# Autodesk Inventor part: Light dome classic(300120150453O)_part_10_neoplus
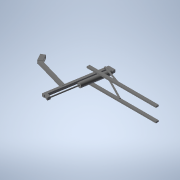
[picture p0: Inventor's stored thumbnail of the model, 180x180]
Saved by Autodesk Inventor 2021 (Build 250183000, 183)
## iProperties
Created: 2026-04
Part Number: Light dome classic(300120150453O)_part_10_neoplus
Material: Generic
Catalog Web Link: www.3dfindit.com
Description: Light dome classic_part_10_neoplus-
Vendor: KINGSPAN
Document SubType Name: Modeling
Designer: psAdmin
Manufacturer: KINGSPAN
Mass: 5302.09 g
Surface Area: 6461.21 cm^2
Volume: 5302.09 cm^3
Density: 1 g/cm^3
Appearance: PSOLRGB-255-255-255
Category: PARTsolutions
Company: KINGSPAN
Title: Light dome classic(300120150453O)_part_10_neoplus
Author: Cadenas PARTsolutions
PSOL_IDENT_0: {$CADENAS_DATA/23d-libs/kingspan_kla/light_dome_classic_neoplus/parts/part_10.prj},291 {VTYP=3D},{NB=
PSOL_IDENT_1: Light dome classic(300120150453O)_part_10_neoplus},{LINA=Light dome classic(300120150453O)_part_10_n
PSOL_IDENT_2: eoplus},{NN=Light dome classic_part_10_neoplus},{DATE=15.07.2024 10:56:16},{GEOMDATE=01.07.2024 07:0
PSOL_IDENT_3: 4:16},{VERSION=},{LINEID=10},{WBVAR=LODLEVEL,L,W,DP,OP,BA,OC},{WBNUMERIC=W}  {NB=Light dome classic(
PSOL_IDENT_4: 300120150453O)_part_10_neoplus},{LINA=Light dome classic(300120150453O)_part_10_neoplus},{KT=DUMMY},
PSOL_IDENT_5: {IDNR=},{PN=Light dome classic},{LODLEVEL=300},{L=120},{W=150},{DRIVE=1},{WX=120,150,180,240,270,300
PSOL_IDENT_6: },{DP=4},{OP=5},{BA=3},{OC=O},{OPX='5','Pneumatic - NRWG F.6 LK'},{LX=1200},{XWX=1500},{HEI=1181.607
PSOL_IDENT_7: },{VER=2},{DPX='3', 'Fixed','1', 'Natural ventilation' ,'4','NSHE', '2', 'NSHEV'}
NB: Light dome classic(300120150453O)_part_10_neoplus
NN: Light dome classic_part_10_neoplus
NBSYN: $PN.($LODLEVEL.$L.$W.$DP.$OP.$BA.$OC.)_part_10_neoplus
LINA: Light dome classic(300120150453O)_part_10_neoplus
CATALOG: Light + Air
PN: Light dome classic
LODLEVEL: 300
L: 120
W: 150
DP: NSHE
OP: Pneumatic - NRWG F.6 LK
BA: PVC base 50 cm
OC: Open
SUPPLIER: KINGSPAN
ARTICLENO: Light dome classic(300120150453O)_part_10_neoplus
BOMINFO: Light dome classic(300120150453O)_part_10_neoplus
CREATOR: CADENAS GmbH
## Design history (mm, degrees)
sketch "Sketch_2"
  geometry: L1 (-524.928, -221.6)-(-511.377, -261.6); L2 (-511.377, -261.6)-(511.377, -261.6); L3 (511.377, -261.6)-(524.928, -221.6); L4 (524.928, -221.6)-(-524.928, -221.6)
  constraints: 8 end point
extrude "Extrusion1" join sketch "Sketch_2" distance "d0" = 20; taper "d1" = 0 deg
sketch "Sketch_1"
  geometry: L1 (542.69, 169.17)-(500.978, 292.296); L2 (500.978, 292.296)-(494.348, 290.05); L3 (494.348, 290.05)-(536.06, 166.924); L4 (536.06, 166.924)-(542.69, 169.17)
  constraints: 8 end point
extrude "Extrusion2" join sketch "Sketch_1" stored distance "d2" = 220; taper "d3" = 0 deg
sketch "Sketch_3"
  geometry: L1 (-494.348, 290.05)-(-500.978, 292.296); L2 (-500.978, 292.296)-(-542.69, 169.17); L3 (-542.69, 169.17)-(-536.06, 166.924); L4 (-536.06, 166.924)-(-494.348, 290.05)
  constraints: 8 end point
extrude "Extrusion3" join sketch "Sketch_3" stored distance "d4" = 220; taper "d5" = 0 deg
sketch "Sketch_4"
  geometry: L1 (-524.928, -221.6)-(-511.377, -261.6); L2 (-511.377, -261.6)-(511.377, -261.6); L3 (511.377, -261.6)-(524.928, -221.6); L4 (524.928, -221.6)-(-524.928, -221.6)
  constraints: 8 end point
extrude "Extrusion4" join sketch "Sketch_4" distance "d6" = 20; taper "d7" = 0 deg
sketch "Sketch_5"
  geometry: L1 (446.574, 66.971)-(48.269, 244.308); L2 (48.269, 244.308)-(40.134, 226.037); L3 (40.134, 226.037)-(438.44, 48.7); L4 (438.44, 48.7)-(446.574, 66.971)
  constraints: 8 end point
extrude "Extrusion5" join sketch "Sketch_5" stored distance "d8" = 172.9; taper "d9" = 0 deg
sketch "Sketch_8"
  geometry: L1 (5, 420)-(53.95, 27.63); L2 (53.95, 27.63)-(118.95, 27.63); L3 (118.95, 27.63)-(167.9, 420); L4 (167.9, 420)-(167.9, 440); L5 (167.9, 440)-(5, 440); L6 (5, 440)-(5, 420)
  constraints: 12 end point
extrude "Extrusion6" cut sketch "Sketch_8" distance "d10" = 30; taper "d11" = 0 deg
sketch "Sketch_15"
  geometry: L1 (0, 0)-(172.9, 0); L2 (172.9, 0)-(172.9, 419.685); L3 (172.9, 419.685)-(120.498, 5); L4 (120.498, 5)-(52.402, 5); L5 (52.402, 5)-(0, 419.685); L6 (0, 419.685)-(0, 0)
  constraints: 12 end point
extrude "Extrusion7" cut sketch "Sketch_15" distance "d12" = 30; taper "d13" = 0 deg
sketch "Sketch_9"
  geometry: L1 (572.69, 832.67)-(538.148, 838.314); L2 (538.148, 838.314)-(536.535, 828.444); L3 (536.535, 828.444)-(478.858, 848.304); L4 (478.858, 848.304)-(472.505, 808.187); L5 (472.505, 808.187)-(529.991, 788.392); L6 (529.991, 788.392)-(408.471, 44.67); L7 (408.471, 44.67)-(340.9, 44.67); L8 (340.9, 44.67)-(340.9, 4.67); L9 (340.9, 4.67)-(437.4, 4.67); L10 (437.4, 4.67)-(572.69, 832.67)
  constraints: 20 end point
extrude "Extrusion8" join sketch "Sketch_9" stored distance "d14" = 35; taper "d15" = 0 deg
sketch "Sketch_13"
  geometry: L1 (356.219, 36.091)-(482.434, 808.551); L2 (482.434, 808.551)-(490.329, 807.261); L3 (490.329, 807.261)-(430.842, 443.189); L4 (430.842, 443.189)-(456.008, 439.077); L5 (456.008, 439.077)-(392.004, 47.361); L6 (392.004, 47.361)-(366.838, 51.473); L7 (366.838, 51.473)-(364.114, 34.801); L8 (364.114, 34.801)-(356.219, 36.091); L9 (356.219, 36.091)-(482.434, 808.551)
  constraints: 18 end point
revolve "Revolution1" sketch "Sketch_13" stored, may be unused: angle "d16" = 360 deg
sketch "Sketch_10"
  geometry: L1 (1012.283, 453.845)-(522.04, 594.42); L2 (522.04, 594.42)-(511.566, 557.892); L3 (511.566, 557.892)-(1001.809, 417.317); L4 (1001.809, 417.317)-(1012.283, 453.845)
  constraints: 8 end point
extrude "Extrusion9" join sketch "Sketch_10" stored distance "d17" = 42; taper "d18" = 0 deg
sketch "Sketch_11"
  geometry: L1 (1070.857, 359.009)-(1017.285, 455.654); L2 (1017.285, 455.654)-(964.808, 426.565); L3 (964.808, 426.565)-(1018.38, 329.92); L4 (1018.38, 329.92)-(1070.857, 359.009)
  constraints: 8 end point
extrude "Extrusion10" join sketch "Sketch_11" stored distance "d19" = 51.4; taper "d20" = 0 deg
sketch "Sketch_12"
  geometry: L1 (10.7, 100)-(10.7, 3); L2 (10.7, 3)-(40.7, 3); L3 (40.7, 3)-(40.7, 100); L4 (40.7, 100)-(10.7, 100)
  constraints: 8 end point
extrude "Extrusion11" cut sketch "Sketch_12" distance "d21" = 60; taper "d22" = 0 deg
sketch "Sketch_17"
  geometry: L1 (555, 166.924)-(555, 292.296); L2 (555, 292.296)-(500.978, 292.296); L3 (500.978, 292.296)-(494.348, 290.05); L4 (494.348, 290.05)-(497.46, 280.864); L5 (497.46, 280.864)-(497.46, 166.924); L6 (497.46, 166.924)-(555, 166.924)
  constraints: 12 end point
extrude "Extrusion12" cut sketch "Sketch_17" stored distance "d23" = 400; taper "d24" = 0 deg
sketch "Sketch_18"
  geometry: L1 (-494.348, 290.05)-(-500.978, 292.296); L2 (-500.978, 292.296)-(-555, 292.296); L3 (-555, 292.296)-(-555, 166.924); L4 (-555, 166.924)-(-498.95, 166.924); L5 (-498.95, 166.924)-(-498.95, 276.466); L6 (-498.95, 276.466)-(-494.348, 290.05)
  constraints: 12 end point
extrude "Extrusion13" cut sketch "Sketch_18" stored distance "d25" = 400; taper "d26" = 0 deg
node "IP_10_XY"
node "IP_10_YZ"
node "IP_10_ZX"
node "IP_10_X"
node "IP_10_Y"
node "IP_10_Z"
node "IP_10_Center"
body "Solid1"
